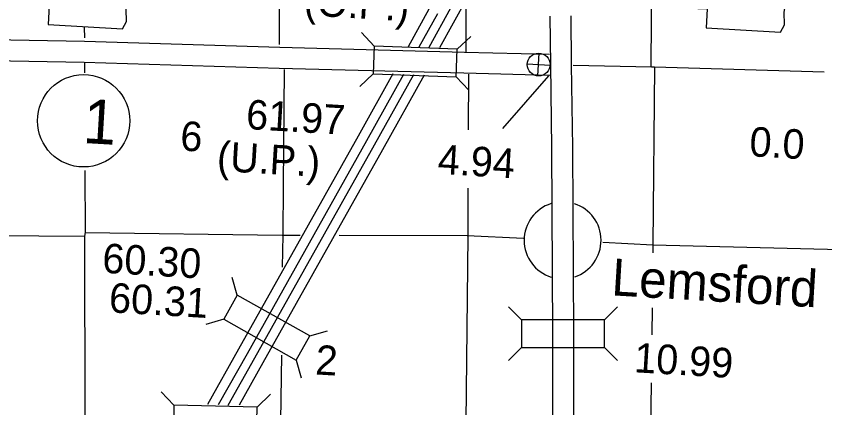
# Model space of a CAD drawing. Extents: x 1366406 to 1373462, y 376856 to 381998.
# Drawn here: x 1368055.7 to 1368242.9, y 380702.1 to 380792.8 of the extents above; entities that cross this region are included whole.
import ezdxf

# ---------------------------------------------------------------- set-up
doc = ezdxf.new("R2010")
doc.units = 0
for name, color, linetype in [('10', 7, 'Continuous'), ('15', 7, 'Continuous'), ('19', 7, 'Continuous'), ('20', 7, 'Continuous'), ('21', 7, 'Continuous'), ('24', 7, 'Continuous'), ('25', 7, 'Continuous'), ('26', 7, 'Continuous'), ('27', 7, 'Continuous'), ('4', 7, 'Continuous'), ('5', 7, 'Continuous'), ('58', 7, 'Continuous')]:
    doc.layers.add(name, color=color, linetype=linetype)

msp = doc.modelspace()

# ---------------------------------------------------------------- linework, layer by layer
at = {"layer": '10'}
for points in [[(1368028.73, 380787.75), (1368071.51, 380787), (1368116.74, 380785.61), (1368159.48, 380784.47), (1368179.21, 380784)], [(1368028.64, 380782.89), (1368071.39, 380782.14), (1368116.6, 380780.75), (1368159.36, 380779.62), (1368179.25, 380779.13)]]:
    msp.add_lwpolyline(points, dxfattribs=at)
at = {"layer": '15'}
for points in [[(1368179.24, 380792.77), (1368179.37, 380781.47)], [(1368184.1, 380792.82), (1368184.22, 380781.53)], [(1368179.37, 380781.47), (1368179.62, 380762.28), (1368179.86, 380719.26), (1368179.86, 380678.41), (1368179.81, 380678.07), (1368179.81, 380678), (1368179.77, 380677.9), (1368179.64, 380677.5), (1368179.23, 380676.43), (1368171.38, 380655.97), (1368165.64, 380640.91), (1368158.72, 380622.92), (1368157.34, 380618.64), (1368157.02, 380617.52), (1368156.88, 380616.77), (1368156.78, 380615.58), (1368156.6, 380614.5), (1368156.54, 380613.64), (1368156.5, 380612.77), (1368156.37, 380611.35), (1368156.29, 380609.59), (1368155.79, 380569.8), (1368155.04, 380526.88)], [(1368184.22, 380781.53), (1368184.48, 380762.32), (1368184.72, 380719.27), (1368184.72, 380678.07), (1368184.65, 380677.56), (1368184.61, 380676.98), (1368184.37, 380676.31), (1368184.22, 380675.87), (1368183.77, 380674.69), (1368175.92, 380654.23), (1368170.18, 380639.17), (1368163.3, 380621.3), (1368161.99, 380617.22), (1368161.75, 380616.4), (1368161.7, 380616.14), (1368161.61, 380614.97), (1368161.43, 380613.91), (1368161.39, 380613.37), (1368161.35, 380612.45), (1368161.22, 380611.02), (1368161.15, 380609.46), (1368160.65, 380569.73), (1368159.9, 380526.79)]]:
    msp.add_lwpolyline(points, dxfattribs=at)
at = {"layer": '19'}
for points in [[(1368242.54, 380876.18), (1368211.74, 380851.41), (1368192.8, 380836.14), (1368188.36, 380832.45), (1368185.73, 380830.41), (1368183.44, 380828.54), (1368180.04, 380825.67), (1368177.39, 380823.43), (1368175.94, 380822.24), (1368173.58, 380820.58), (1368171.64, 380818.83), (1368170, 380817.04), (1368168.64, 380815.26), (1368167.39, 380813.73), (1368165.94, 380811.76), (1368164.9, 380809.99), (1368163.31, 380807.32), (1368161.24, 380803.79), (1368151.24, 380785.5)], [(1368242.52, 380873.3), (1368213.14, 380849.68), (1368194.21, 380834.41), (1368189.76, 380830.71), (1368187.12, 380828.66), (1368184.86, 380826.83), (1368181.48, 380823.97), (1368178.82, 380821.72), (1368177.29, 380820.46), (1368174.97, 380818.84), (1368173.21, 380817.25), (1368171.71, 380815.61), (1368170.39, 380813.88), (1368169.15, 380812.36), (1368167.8, 380810.53), (1368166.82, 380808.86), (1368165.23, 380806.19), (1368163.18, 380802.69), (1368153.73, 380785.42)], [(1368151.27, 380794.41), (1368146.41, 380785.67)], [(1368153.21, 380793.33), (1368148.91, 380785.59)], [(1368142.9, 380779.38), (1368134.89, 380764.96), (1368107.18, 380715.67), (1368099.97, 380702.82)], [(1368145.4, 380779.29), (1368136.83, 380763.87), (1368109.13, 380714.58), (1368102.48, 380702.75)], [(1368147.68, 380779.21), (1368138.6, 380762.88), (1368110.89, 380713.59), (1368104.73, 380702.62)], [(1368150.18, 380779.12), (1368140.54, 380761.8), (1368112.83, 380712.5), (1368107.33, 380702.7)]]:
    msp.add_lwpolyline(points, dxfattribs=at)
at = {"layer": '20'}
for p, q in [((1368138.58, 380785.83), (1368135.67, 380788.96)), ((1368157.82, 380785.16), (1368160.95, 380788.08)), ((1368138.36, 380779.42), (1368135.23, 380776.5)), ((1368157.59, 380778.75), (1368160.51, 380775.62)), ((1368106.87, 380728.15), (1368105.72, 380732.27)), ((1368172.66, 380722.46), (1368169.64, 380725.48)), ((1368191.91, 380722.46), (1368194.93, 380725.48)), ((1368103.73, 380722.56), (1368099.61, 380721.4)), ((1368123.65, 380718.72), (1368127.77, 380719.87)), ((1368172.66, 380716.04), (1368169.64, 380713.02)), ((1368191.91, 380716.04), (1368194.93, 380713.02)), ((1368120.51, 380713.12), (1368121.66, 380709.01)), ((1368092.22, 380702.69), (1368089.27, 380705.78)), ((1368111.46, 380702.24), (1368114.56, 380705.2))]:
    msp.add_line(p, q, dxfattribs=at)
for points in [[(1368138.36, 380779.42), (1368157.59, 380778.75), (1368157.82, 380785.16), (1368138.58, 380785.83)], [(1368123.65, 380718.72), (1368106.87, 380728.15), (1368103.73, 380722.56), (1368120.51, 380713.12)], [(1368172.66, 380716.04), (1368191.91, 380716.04), (1368191.91, 380722.46), (1368172.66, 380722.46)], [(1368092.08, 380696.27), (1368111.32, 380695.83), (1368111.46, 380702.24), (1368092.22, 380702.69)]]:
    msp.add_lwpolyline(points, close=True, dxfattribs=at)
at = {"layer": '21'}
for points in [[(1368060.75, 380816.77), (1368061.5, 380808.49), (1368060.22, 380796.07), (1368061.27, 380795.33), (1368063.32, 380795.21), (1368063.06, 380790.83), (1368080.3, 380789.81), (1368081.23, 380791.54), (1368081.12, 380794.43), (1368081.73, 380797.69), (1368083.38, 380800.2), (1368084.45, 380802.06), (1368085.94, 380804.03), (1368086.89, 380806.17), (1368087.68, 380807.91), (1368089, 380809.34), (1368089.33, 380810.28), (1368088.82, 380811), (1368084.58, 380811.25), (1368085.65, 380813.11), (1368085.86, 380814.33), (1368085.35, 380815.31)], [(1368213.09, 380816.02), (1368213.84, 380807.74), (1368212.56, 380795.32), (1368213.61, 380794.58), (1368215.67, 380794.46), (1368215.41, 380790.08), (1368232.65, 380789.06), (1368233.57, 380790.79), (1368233.47, 380793.68), (1368234.07, 380796.94), (1368235.73, 380799.45), (1368236.8, 380801.31), (1368238.29, 380803.28), (1368239.24, 380805.42), (1368240.03, 380807.16), (1368241.35, 380808.59), (1368241.68, 380809.53), (1368241.17, 380810.25), (1368236.93, 380810.5), (1368238, 380812.36), (1368238.21, 380813.58), (1368237.7, 380814.56)]]:
    msp.add_lwpolyline(points, close=True, dxfattribs=at)
at = {"layer": '24'}
for start, end in [(107.5185, 252.9042), (288.3821, 72.2801)]:
    msp.add_arc((1368182.21, 380740.86), 8.91, start, end, dxfattribs=at)
at = {"layer": '25'}
msp.add_line((1368178.92, 380778.96), (1368168.31, 380766.76), dxfattribs=at)
at = {"layer": '26'}
for p, q in [((1368176.5, 380778.94), (1368176.81, 380784.2)), ((1368174.03, 380781.73), (1368179.29, 380781.42))]:
    msp.add_line(p, q, dxfattribs=at)
msp.add_circle((1368176.66, 380781.57), 2.63, dxfattribs=at)
at = {"layer": '27'}
msp.add_circle((1368071.3, 380768.54), 10.69, dxfattribs=at)
at = {"layer": '4'}
for points in [[(1368071.45, 380790.13), (1368071.48, 380787.73)], [(1368071.52, 380781.87), (1368071.53, 380779.66)], [(1368184.65, 380781.46), (1368202.79, 380781.02), (1368203.49, 380781.07), (1368242.78, 380779.87)], [(1368071.59, 380757.01), (1368071.63, 380742.65), (1368071.51, 380741.79), (1368071.55, 380699.6), (1368071.48, 380698.76), (1368071.81, 380656.42)]]:
    msp.add_lwpolyline(points, dxfattribs=at)
at = {"layer": '5'}
for points in [[(1368202.93, 380841.25), (1368202.95, 380824.04), (1368202.65, 380781.1)], [(1368116.59, 380827.59), (1368116.58, 380826.69), (1368116.61, 380791.18)], [(1368159.77, 380795.81), (1368159.77, 380784.47)], [(1368116.61, 380791.18), (1368116.61, 380786.21)], [(1368203.49, 380781.07), (1368203.12, 380739.79), (1368203.09, 380737.98)], [(1368117.76, 380780.46), (1368117.5, 380753.64)], [(1368160.44, 380779.37), (1368160.37, 380766.45)], [(1368117.5, 380753.64), (1368117.39, 380742.09), (1368117.3, 380734.67)], [(1368160.3, 380752.91), (1368160.24, 380741.91), (1368159.79, 380698.79), (1368159.34, 380655.53), (1368159.29, 380651.53)], [(1367986.46, 380742.84), (1368029.03, 380742.12), (1368071.51, 380741.79)], [(1368071.63, 380742.65), (1368117.29, 380742.06), (1368121.47, 380742.05)], [(1368130.49, 380742.03), (1368160.11, 380741.98), (1368173.15, 380741.32)], [(1368191.52, 380740.41), (1368203.07, 380739.83), (1368246.65, 380738.74), (1368289.2, 380737.19)], [(1368202.92, 380725.22), (1368202.84, 380718.97)], [(1368117.08, 380714.28), (1368116.9, 380699.02), (1368116.53, 380656.23), (1368116.5, 380653.76)], [(1368202.7, 380707.87), (1368202.55, 380696.63), (1368202.45, 380676.74)]]:
    msp.add_lwpolyline(points, dxfattribs=at)

# ---------------------------------------------------------------- texts
at = {"layer": '20'}
msp.add_text('2', height=6.84, rotation=356.6294, dxfattribs=at).set_placement((1368124.83, 380709.81))
at = {"layer": '24'}
msp.add_text('Lemsford', height=8.554, rotation=356.6294, dxfattribs=at).set_placement((1368193.38, 380728.13))
at = {"layer": '25'}
for s, p in [('0.0', (1368225.33, 380760.36)), ('4.94', (1368153.16, 380756.26))]:
    msp.add_text(s, height=6.843, rotation=356.6294, dxfattribs=at).set_placement(p)
at = {"layer": '27'}
msp.add_text('1', height=10.26, rotation=356.6294, dxfattribs=at).set_placement((1368071, 380763.42))
at = {"layer": '5'}
msp.add_text('6', height=6.84, rotation=356.6294, dxfattribs=at).set_placement((1368093.54, 380761.68))
at = {"layer": '58'}
for s, p in [('(O.P.)', (1368122.17, 380793)), ('61.97', (1368108.78, 380766.65)), ('(U.P.)', (1368102.04, 380756.95)), ('60.30', (1368075.49, 380733.36)), ('60.31', (1368077.04, 380724.21)), ('10.99', (1368198.64, 380710.31))]:
    msp.add_text(s, height=6.843, rotation=356.6294, dxfattribs=at).set_placement(p)

doc.saveas('drawing.dxf')
